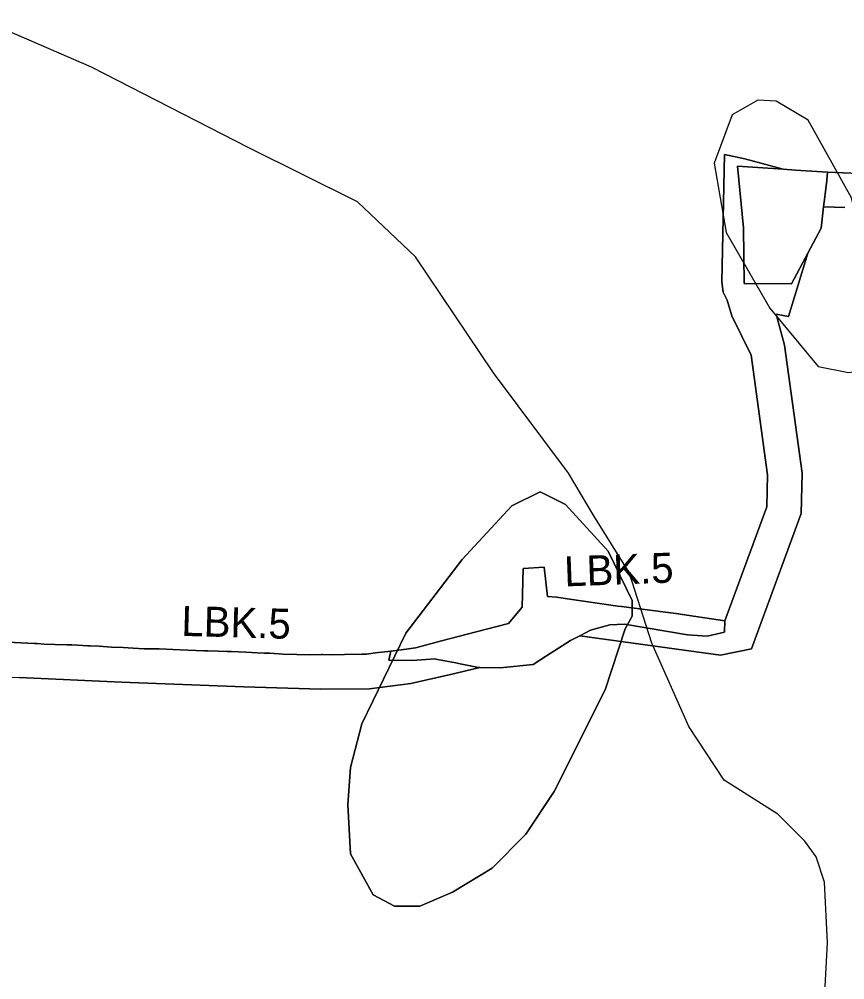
# Model space of a CAD drawing. Extents: x -555426 to -553015, y -1186745 to -1182595.
# Drawn here: x -555067.9 to -554710.4, y -1186406.3 to -1185990.3 of the extents above; entities that cross this region are included whole.
import ezdxf

# ---------------------------------------------------------------- set-up
doc = ezdxf.new("R2010")
doc.units = 0
for name, color, linetype in [('Level 12', 7, 'Continuous'), ('svahove_deformace', 7, 'Continuous'), ('USES_ID', 7, 'Continuous'), ('USES_LBK_navrh', 7, 'Continuous'), ('USES_LBK_stav', 7, 'Continuous')]:
    doc.layers.add(name, color=color, linetype=linetype)

msp = doc.modelspace()

# ---------------------------------------------------------------- linework, layer by layer
at = {"layer": 'Level 12'}
for points in [[(-554707.7, -1186057.02), (-554717.81, -1186056.56), (-554731.68, -1186055.61), (-554737.11, -1186055.23), (-554753.62, -1186050.71), (-554762.47, -1186048.86), (-554763.69, -1186104.04), (-554763.13, -1186108.53), (-554761.3, -1186111.92), (-554759.33, -1186118.73), (-554750.96, -1186135.85), (-554743.83, -1186187.67), (-554744.21, -1186201.47), (-554762.32, -1186250.8), (-554783.59, -1186247.69), (-554807.08, -1186244.72), (-554808.67, -1186244.5), (-554830.46, -1186241.38), (-554835.28, -1186240.65), (-554839.16, -1186240.36), (-554840.62, -1186227.66), (-554849.68, -1186228.24), (-554850.12, -1186244.95), (-554855.96, -1186252.02), (-554869.97, -1186255.68), (-554877.27, -1186257.56), (-554885.02, -1186259.59), (-554893.59, -1186261.84), (-554896.34, -1186262.51), (-554900.36, -1186263.12), (-554906.96, -1186263.94), (-554913.63, -1186264.75), (-554917.47, -1186265.28), (-554919.39, -1186265.33), (-554927.11, -1186265.47), (-554932.26, -1186265.55), (-554936.56, -1186265.5), (-554937.11, -1186265.47), (-554942.03, -1186265.63), (-554947.66, -1186265.42), (-554953.66, -1186265.32), (-554959.36, -1186264.92), (-554961.69, -1186264.81), (-554964.83, -1186264.67), (-554969.85, -1186264.42), (-554976.07, -1186264.1), (-554978.07, -1186264.16), (-554981.59, -1186263.95), (-554986.25, -1186263.91), (-554987.98, -1186263.78), (-554994.91, -1186263.58), (-555001.35, -1186263.21), (-555004.22, -1186263.18), (-555007.26, -1186263.05), (-555012.37, -1186262.95), (-555013.89, -1186263.01), (-555018.64, -1186262.69), (-555020.77, -1186262.57), (-555022.88, -1186262.45), (-555027.97, -1186262.21), (-555033.35, -1186261.86), (-555037.22, -1186261.67), (-555038.25, -1186261.63), (-555042.62, -1186261.45), (-555045.15, -1186261.2), (-555047.35, -1186261.3), (-555052.31, -1186261.05), (-555057.13, -1186260.95), (-555060.21, -1186260.69), (-555061.43, -1186260.68), (-555067.24, -1186260.4), (-555072.69, -1186260.16)], [(-555089.85, -1186274.46), (-555067.93, -1186275.38), (-555023.66, -1186277.43), (-554970.61, -1186279.4), (-554937.28, -1186280.48), (-554916.25, -1186280.25), (-554898.31, -1186277.98), (-554881.21, -1186274.1), (-554868.43, -1186271.13), (-554859.71, -1186271.15), (-554845.34, -1186269.8), (-554839.51, -1186266.06), (-554829.17, -1186259.42), (-554825.12, -1186257.3), (-554764.26, -1186265.68), (-554750.84, -1186263.05), (-554729.28, -1186204.34), (-554728.8, -1186186.85), (-554736.43, -1186131.42), (-554740.11, -1186118.07), (-554734.72, -1186119), (-554726.42, -1186091.6), (-554720.62, -1186080.75), (-554719.54, -1186071.5), (-554710.39, -1186071.91)]]:
    msp.add_lwpolyline(points, dxfattribs=at)
at = {"layer": 'svahove_deformace'}
for p, q in [((-554812.92, -1186220.67), (-554831.3, -1186200.45)), ((-554876.03, -1186224.35), (-554900.54, -1186256.21)), ((-554802.5, -1186242.12), (-554812.92, -1186220.67)), ((-554802.5, -1186242.12), (-554802.5, -1186248.86)), ((-554802.5, -1186248.86), (-554802.5, -1186242.12)), ((-554805.57, -1186254.37), (-554802.5, -1186248.86)), ((-554814.14, -1186280.72), (-554836.2, -1186324.83)), ((-554924.43, -1186314.42), (-554925.66, -1186330.35)), ((-554848.46, -1186343.22), (-554836.2, -1186324.83)), ((-554924.43, -1186351.79), (-554925.66, -1186330.35)), ((-554925.66, -1186330.35), (-554924.43, -1186351.79)), ((-554863.16, -1186357.92), (-554848.46, -1186343.22)), ((-554924.43, -1186351.79), (-554914.63, -1186369.56)), ((-554914.63, -1186369.56), (-554905.44, -1186374.46)), ((-554905.44, -1186374.46), (-554894.41, -1186374.46))]:
    msp.add_line(p, q, dxfattribs=at)
for points in [[(-554721.01, -1186449.83), (-554717.95, -1186390.39), (-554719.17, -1186364.05), (-554722.85, -1186353.02), (-554727.75, -1186346.28), (-554739.39, -1186334.64), (-554762.68, -1186319.93), (-554777.99, -1186296.65), (-554793.92, -1186260.5), (-554803.73, -1186229.86), (-554819.05, -1186205.36), (-554830.07, -1186186.97), (-554862.55, -1186143.47), (-554896.25, -1186093.23), (-554921.37, -1186069.33), (-554968.55, -1186046.05), (-555036.56, -1186011.13), (-555073.32, -1185995.19), (-555095.99, -1185990.29), (-555115.6, -1185994.58), (-555149.91, -1186019.09), (-555204.44, -1186079.75), (-555227.11, -1186119.58), (-555248.89, -1186153.45)], [(-554692.79, -1186130.61), (-554696.09, -1186115.11), (-554707.43, -1186067.62), (-554726.31, -1186034.06), (-554740.14, -1186025.74), (-554747.99, -1186025.4), (-554759.18, -1186031.7), (-554766.95, -1186052.71), (-554761.79, -1186082.71), (-554742.79, -1186115.49), (-554721.91, -1186140.64), (-554708.85, -1186143.31), (-554698.33, -1186141.67), (-554692.79, -1186130.61)], [(-554876.03, -1186224.35), (-554854.58, -1186201.07), (-554842.33, -1186194.94), (-554831.3, -1186200.45), (-554812.92, -1186220.67), (-554802.5, -1186242.12)], [(-554831.3, -1186200.45), (-554842.33, -1186194.94), (-554854.58, -1186201.07), (-554876.03, -1186224.35)], [(-554925.66, -1186330.35), (-554924.43, -1186314.42), (-554919.53, -1186295.42), (-554900.54, -1186256.21), (-554876.03, -1186224.35)], [(-554802.5, -1186248.86), (-554805.57, -1186254.37), (-554814.14, -1186280.72)], [(-554900.54, -1186256.21), (-554919.53, -1186295.42), (-554924.43, -1186314.42)], [(-554836.2, -1186324.83), (-554814.14, -1186280.72), (-554805.57, -1186254.37)], [(-554836.2, -1186324.83), (-554848.46, -1186343.22), (-554863.16, -1186357.92), (-554880.32, -1186368.34)], [(-554905.44, -1186374.46), (-554914.63, -1186369.56), (-554924.43, -1186351.79)], [(-554894.41, -1186374.46), (-554880.32, -1186368.34), (-554863.16, -1186357.92)], [(-554880.32, -1186368.34), (-554894.41, -1186374.46), (-554905.44, -1186374.46)]]:
    msp.add_lwpolyline(points, dxfattribs=at)
at = {"layer": 'USES_LBK_navrh'}
for p, q in [((-554737.11, -1186055.23), (-554756.79, -1186053.88)), ((-554756.79, -1186053.88), (-554754.21, -1186080.59)), ((-554718.22, -1186060.11), (-554717.81, -1186056.56)), ((-554719.05, -1186067.25), (-554718.22, -1186060.11)), ((-554719.54, -1186071.5), (-554719.05, -1186067.25)), ((-554710.39, -1186071.91), (-554719.54, -1186071.5)), ((-554754.21, -1186080.59), (-554754.02, -1186104.78)), ((-554733.53, -1186104.88), (-554726.42, -1186091.6)), ((-554754.02, -1186104.78), (-554733.53, -1186104.88)), ((-554762.32, -1186250.8), (-554744.21, -1186201.47)), ((-554729.28, -1186204.34), (-554750.84, -1186263.05)), ((-554817.93, -1186254.2), (-554812.08, -1186252.63)), ((-554812.08, -1186252.63), (-554805.74, -1186252.36)), ((-554805.74, -1186252.36), (-554796.4, -1186253.91)), ((-554762.42, -1186255.74), (-554762.32, -1186250.8)), ((-554825.12, -1186257.3), (-554820.52, -1186254.89)), ((-554764.26, -1186265.68), (-554825.12, -1186257.3)), ((-554820.52, -1186254.89), (-554817.93, -1186254.2)), ((-554796.4, -1186253.91), (-554778.46, -1186256.89)), ((-554778.46, -1186256.89), (-554769.94, -1186257.54)), ((-554769.94, -1186257.54), (-554762.42, -1186255.74)), ((-555067.24, -1186260.4), (-555061.43, -1186260.68)), ((-555042.62, -1186261.45), (-555038.25, -1186261.63)), ((-555018.64, -1186262.69), (-555013.89, -1186263.01)), ((-554978.07, -1186264.16), (-554976.07, -1186264.1)), ((-554932.26, -1186265.55), (-554927.11, -1186265.47)), ((-554906.96, -1186263.94), (-554907.83, -1186267.84)), ((-554750.84, -1186263.05), (-554764.26, -1186265.68)), ((-554907.83, -1186267.84), (-554897.58, -1186268.01)), ((-554897.58, -1186268.01), (-554887.87, -1186267.31)), ((-554887.87, -1186267.31), (-554886.77, -1186267.56)), ((-554886.77, -1186267.56), (-554878.85, -1186269.12)), ((-554878.85, -1186269.12), (-554877.64, -1186269.36)), ((-554877.64, -1186269.36), (-554869.06, -1186271.01)), ((-554869.06, -1186271.01), (-554868.43, -1186271.13)), ((-554937.28, -1186280.48), (-554970.61, -1186279.4))]:
    msp.add_line(p, q, dxfattribs=at)
for points in [[(-554750.96, -1186135.85), (-554759.33, -1186118.73), (-554761.3, -1186111.92), (-554763.13, -1186108.53), (-554763.69, -1186104.04), (-554762.47, -1186048.86), (-554753.62, -1186050.71), (-554737.11, -1186055.23)], [(-554717.81, -1186056.56), (-554707.7, -1186057.02), (-554595.17, -1186093.44)], [(-554726.42, -1186091.6), (-554734.72, -1186119), (-554740.11, -1186118.07), (-554736.43, -1186131.42)], [(-554736.43, -1186131.42), (-554728.8, -1186186.85), (-554729.28, -1186204.34)], [(-554744.21, -1186201.47), (-554743.83, -1186187.67), (-554750.96, -1186135.85)], [(-555077.96, -1186259.94), (-555072.69, -1186260.16), (-555067.24, -1186260.4)], [(-555061.43, -1186260.68), (-555060.21, -1186260.69), (-555057.13, -1186260.95), (-555052.31, -1186261.05)], [(-555052.31, -1186261.05), (-555047.35, -1186261.3), (-555045.15, -1186261.2), (-555042.62, -1186261.45)], [(-555038.25, -1186261.63), (-555037.22, -1186261.67), (-555033.35, -1186261.86), (-555027.97, -1186262.21)], [(-555027.97, -1186262.21), (-555022.88, -1186262.45), (-555020.77, -1186262.57), (-555018.64, -1186262.69)], [(-555013.89, -1186263.01), (-555012.37, -1186262.95), (-555007.26, -1186263.05), (-555004.22, -1186263.18)], [(-555004.22, -1186263.18), (-555001.35, -1186263.21), (-554994.91, -1186263.58), (-554987.98, -1186263.78)], [(-554987.98, -1186263.78), (-554986.25, -1186263.91), (-554981.59, -1186263.95), (-554978.07, -1186264.16)], [(-554976.07, -1186264.1), (-554969.85, -1186264.42), (-554964.83, -1186264.67), (-554961.69, -1186264.81)], [(-554961.69, -1186264.81), (-554959.36, -1186264.92), (-554953.66, -1186265.32), (-554947.66, -1186265.42), (-554942.03, -1186265.63)], [(-554942.03, -1186265.63), (-554937.11, -1186265.47), (-554936.56, -1186265.5), (-554932.26, -1186265.55)], [(-554927.11, -1186265.47), (-554919.39, -1186265.33), (-554917.47, -1186265.28), (-554913.63, -1186264.75), (-554906.96, -1186263.94)], [(-554868.43, -1186271.13), (-554881.21, -1186274.1), (-554898.31, -1186277.98)], [(-554970.61, -1186279.4), (-555023.66, -1186277.43), (-555067.93, -1186275.38)], [(-554898.31, -1186277.98), (-554916.25, -1186280.25), (-554937.28, -1186280.48)]]:
    msp.add_lwpolyline(points, dxfattribs=at)
at = {"layer": 'USES_LBK_stav'}
for p, q in [((-554754.21, -1186080.59), (-554756.79, -1186053.88)), ((-554756.79, -1186053.88), (-554737.11, -1186055.23)), ((-554717.81, -1186056.56), (-554718.22, -1186060.11)), ((-554718.22, -1186060.11), (-554719.05, -1186067.25)), ((-554719.05, -1186067.25), (-554719.54, -1186071.5)), ((-554754.02, -1186104.78), (-554754.21, -1186080.59)), ((-554726.42, -1186091.6), (-554733.53, -1186104.88)), ((-554733.53, -1186104.88), (-554754.02, -1186104.78)), ((-554812.08, -1186252.63), (-554817.93, -1186254.2)), ((-554805.74, -1186252.36), (-554812.08, -1186252.63)), ((-554796.4, -1186253.91), (-554805.74, -1186252.36)), ((-554762.32, -1186250.8), (-554762.42, -1186255.74)), ((-554820.52, -1186254.89), (-554825.12, -1186257.3)), ((-554817.93, -1186254.2), (-554820.52, -1186254.89)), ((-554778.46, -1186256.89), (-554796.4, -1186253.91)), ((-554769.94, -1186257.54), (-554778.46, -1186256.89)), ((-554762.42, -1186255.74), (-554769.94, -1186257.54)), ((-554907.83, -1186267.84), (-554906.96, -1186263.94)), ((-554897.58, -1186268.01), (-554907.83, -1186267.84)), ((-554887.87, -1186267.31), (-554897.58, -1186268.01)), ((-554886.77, -1186267.56), (-554887.87, -1186267.31)), ((-554878.85, -1186269.12), (-554886.77, -1186267.56)), ((-554877.64, -1186269.36), (-554878.85, -1186269.12)), ((-554869.06, -1186271.01), (-554877.64, -1186269.36)), ((-554868.43, -1186271.13), (-554869.06, -1186271.01))]:
    msp.add_line(p, q, dxfattribs=at)
for points in [[(-554737.11, -1186055.23), (-554731.68, -1186055.61), (-554717.81, -1186056.56)], [(-554719.54, -1186071.5), (-554720.62, -1186080.75), (-554726.42, -1186091.6)], [(-554906.96, -1186263.94), (-554900.36, -1186263.12), (-554896.34, -1186262.51), (-554893.59, -1186261.84), (-554885.02, -1186259.59), (-554877.27, -1186257.56), (-554869.97, -1186255.68), (-554855.96, -1186252.02), (-554850.12, -1186244.95), (-554849.68, -1186228.24), (-554840.62, -1186227.66), (-554839.16, -1186240.36), (-554835.28, -1186240.65), (-554830.46, -1186241.38), (-554808.67, -1186244.5), (-554807.08, -1186244.72), (-554783.59, -1186247.69), (-554762.32, -1186250.8)], [(-554825.12, -1186257.3), (-554829.17, -1186259.42), (-554839.51, -1186266.06), (-554845.34, -1186269.8), (-554859.71, -1186271.15), (-554868.43, -1186271.13)]]:
    msp.add_lwpolyline(points, dxfattribs=at)

# ---------------------------------------------------------------- texts
at = {"layer": 'USES_ID'}
for rotation, p in [(2.1036, (-554831.7, -1186235.98)), (358.3857, (-554997.83, -1186257.36))]:
    msp.add_text('LBK.5', height=13, rotation=rotation, dxfattribs=at).set_placement(p)

doc.saveas('drawing.dxf')
